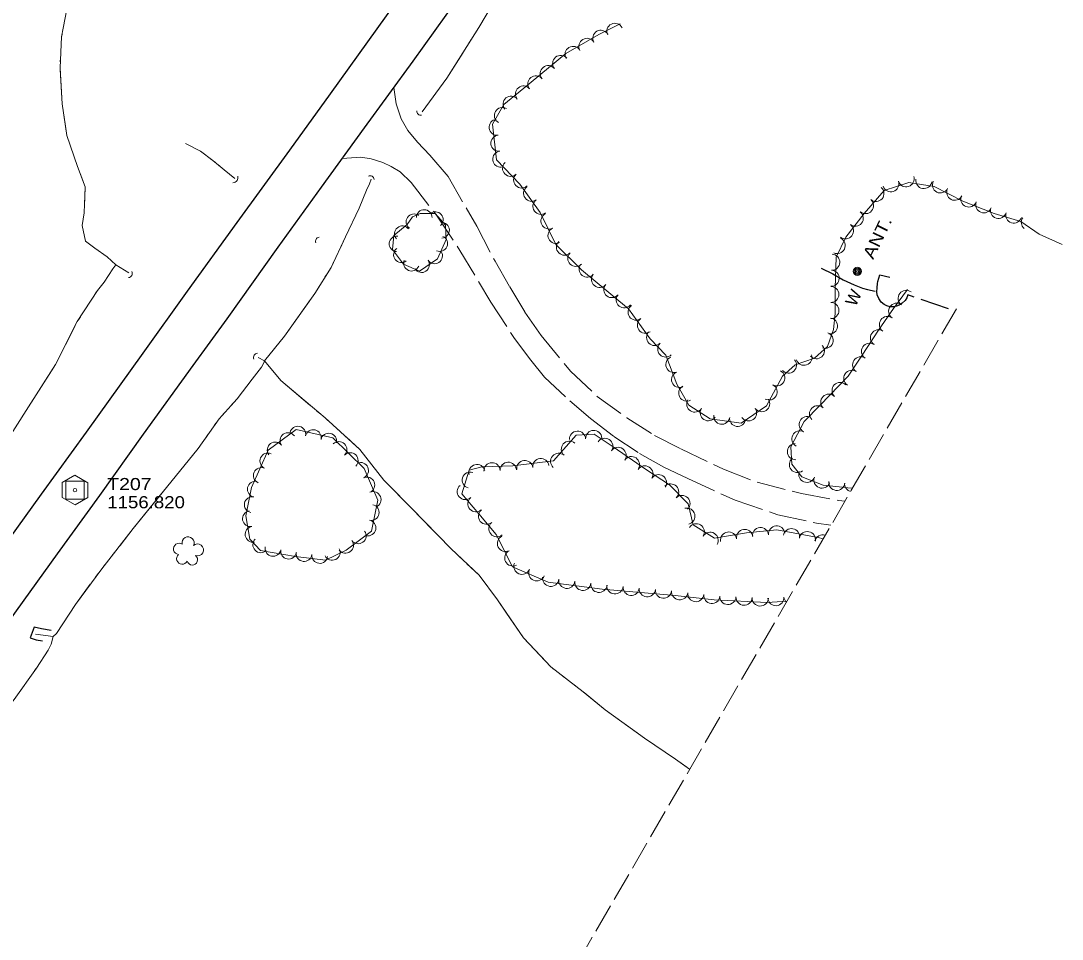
# Model space of a CAD drawing. Extents: x 300582 to 302999, y 51302 to 53600.
# Drawn here: x 301953 to 302469, y 52259 to 52714 of the extents above; entities that cross this region are included whole.
import ezdxf

# ---------------------------------------------------------------- set-up
doc = ezdxf.new("R2010")
doc.units = 0
doc.header["$LTSCALE"] = 2.4
doc.linetypes.add('LONG_DASHED', pattern=[7.5, 6, -1.5])
for name, color, linetype, lineweight in [('11', 7, 'Continuous', 25), ('12', 7, 'LONG_DASHED', 25), ('14', 7, 'Continuous', 13), ('15', 7, 'Continuous', 13), ('17', 7, 'LONG_DASHED', 13), ('18', 7, 'Continuous', 13), ('19', 7, 'Continuous', 13), ('4', 7, 'Continuous', 13), ('5', 7, 'Continuous', 13)]:
    doc.layers.add(name, color=color, linetype=linetype, lineweight=lineweight)

msp = doc.modelspace()

# ---------------------------------------------------------------- linework, layer by layer
at = {"layer": '11'}
for points in [[(301790.631, 52240.188), (301811.362, 52268.952), (301834.758, 52301.902), (301855.568, 52330.847), (301876.524, 52359.962), (301895.034, 52385.599), (301914.633, 52412.642), (301935.324, 52441.425), (301962.819, 52479.632), (301985.088, 52510.301), (302013.182, 52549.479), (302035.259, 52580.267), (302059.745, 52614.271), (302085.845, 52650.072), (302106.047, 52677.908), (302129.22, 52710.139), (302151.517, 52741.398), (302166.099, 52761.911), (302177.391, 52776.932)], [(301819.169, 52239.529), (301841.265, 52270.036), (301866.294, 52304.928), (301887.003, 52333.725), (301907.637, 52362.366), (301930.485, 52394.198), (301950.448, 52421.855), (301970.827, 52449.98), (301991.782, 52478.95), (302013.431, 52509.265), (302038.019, 52543.286), (302054.779, 52566.538), (302080.08, 52602.004), (302101.586, 52631.767), (302122.935, 52661.135), (302147.043, 52694.203), (302168.841, 52724.743), (302184.37, 52746.358), (302194.801, 52761.275)]]:
    msp.add_lwpolyline(points, dxfattribs=at)
at = {"layer": '12'}
msp.add_lwpolyline([(302412.324, 52571.355), (302392.142, 52578.364), (302391.592, 52576.882), (302390.82, 52575.633), (302389.309, 52574.188), (302387.835, 52573.282), (302386.511, 52572.674), (302385.176, 52572.419), (302383.431, 52572.401), (302381.791, 52572.936), (302380.474, 52573.541), (302378.989, 52574.814), (302377.734, 52576.481), (302377, 52578.314), (302376.818, 52579.921), (302376.887, 52581.821), (302377.109, 52583.93), (302377.344, 52585.019), (302378.297, 52588.252), (302383.199, 52587.174)], dxfattribs=at)
at = {"layer": '14'}
for centre, radius in [((302367.131, 52590.036), 2.018), ((302367.119, 52590.041), 1.518), ((302367.155, 52590.023), 1.008), ((302367.149, 52590.032), 0.502)]:
    msp.add_circle(centre, radius, dxfattribs=at)
at = {"layer": '15', "lineweight": 25}
for points in [[(302349.178, 52591.663), (302354.932, 52588.828), (302360.017, 52585.876), (302365.531, 52583.276), (302369.747, 52581.65), (302372.103, 52580.941), (302375.904, 52580.21)], [(301967.692, 52412.047), (301962.906, 52412.842), (301959.178, 52413.746), (301957.319, 52408.44), (301960.295, 52407.459), (301963.346, 52406.897)]]:
    msp.add_lwpolyline(points, dxfattribs=at)
at = {"layer": '15'}
for centre, radius, start, end in [((302150.768, 52669.29), 1.964, 175.22165, 281.46122), ((302057.698, 52636.468), 2.529, 270.89891, 17.13847), ((302125.64, 52635.321), 2.043, 6.63435, 112.87391), ((302100.624, 52604.928), 1.993, 96.56607, 202.80563), ((302005.683, 52589.08), 2.18, 277.01434, 23.25391), ((302070.086, 52547.318), 2.165, 94.45138, 200.69094)]:
    msp.add_arc(centre, radius, start, end, dxfattribs=at)
at = {"layer": '17'}
for points in [[(302137.507, 52681.123), (302138.673, 52672.939), (302141.046, 52665.53), (302144.429, 52659.784), (302149.198, 52653.947), (302155.256, 52647.592), (302164.29, 52637), (302178.497, 52612.321), (302187.622, 52595.048), (302194.853, 52582.339), (302202.405, 52569.785), (302210.437, 52558.284), (302225.023, 52540.531), (302238.225, 52528.068), (302252.906, 52517.475), (302266.565, 52508.757), (302279.686, 52502.085), (302300.759, 52491.925), (302317.47, 52485.522), (302339.406, 52479.863), (302357.802, 52476.441), (302361.026, 52476.221)], [(302111.903, 52645.959), (302121.155, 52646.61), (302126.158, 52645.743), (302131.979, 52643.853), (302136.164, 52642), (302140.654, 52639.315), (302146, 52633.97), (302158.84, 52617.405), (302170.188, 52600.391), (302185.544, 52574.768), (302197.193, 52556.794), (302205.28, 52546.034), (302212.064, 52537.611), (302224.644, 52525.831), (302234.848, 52517.023), (302246.446, 52508.186), (302259.104, 52499.789), (302271.315, 52493.01), (302283.18, 52487.312), (302306.521, 52476.667), (302327.66, 52469.374), (302346.864, 52465.211), (302354.049, 52464.179)]]:
    msp.add_lwpolyline(points, dxfattribs=at)
at = {"layer": '18'}
for points in [[(302249.628, 52712.569), (302238.953, 52707.292), (302222.714, 52697.865), (302205.556, 52683.77), (302191.988, 52672.657), (302186.375, 52662.958), (302188.337, 52645.265), (302199.911, 52633.177), (302209.887, 52619.215), (302217.684, 52603.332), (302230.387, 52590.71), (302253.707, 52571.451), (302264.408, 52556.546), (302272.204, 52548.49), (302277.647, 52534.184), (302283.552, 52523.63), (302294.168, 52516.886), (302309.541, 52514.798), (302322.05, 52523.456), (302330.068, 52538.117), (302336.272, 52543.702), (302345.958, 52547.034), (302352.309, 52552.847), (302355.269, 52561.217), (302356.12, 52569.16), (302356.053, 52581.657), (302356.65, 52597.022), (302361.478, 52607.004), (302370.544, 52618.585), (302380.398, 52630.129), (302392.614, 52634.076), (302405.19, 52632.076), (302419.383, 52624.752), (302434.98, 52618.675), (302448.151, 52614.661), (302457.265, 52608.373), (302468.617, 52603.279)], [(302392.05, 52581.082), (302384.967, 52571.586), (302377.562, 52560.885), (302369.438, 52548.508), (302362.6, 52538.089), (302348.629, 52523.702), (302340.733, 52515.668), (302334.219, 52502.986), (302334.651, 52494.407), (302339.646, 52488.162), (302350.191, 52484.105), (302361.258, 52482.918), (302362.367, 52482.776), (302364.752, 52482.654)], [(302350.187, 52457.513), (302347.789, 52458.215), (302327.162, 52462.01), (302312.228, 52460.438), (302296.382, 52457.867), (302285.831, 52464.342), (302283.282, 52474.851), (302274.015, 52484.283), (302262.632, 52491.644), (302246.197, 52503), (302236.784, 52509.315), (302227.795, 52508.899), (302216.623, 52496.201), (302196.347, 52493.628), (302181.116, 52493.111), (302174.693, 52491.524), (302171.116, 52479.77), (302179.643, 52469.913), (302188.121, 52459.703), (302196.293, 52443.57), (302213.917, 52435.96), (302240.753, 52432.623), (302276.882, 52429.399), (302296.164, 52427.182), (302322.431, 52425.924), (302332.313, 52426.66)]]:
    msp.add_lwpolyline(points, dxfattribs=at)
for points in [[(302137.384, 52607.695), (302136.765, 52600.748), (302142.252, 52593.56), (302150.106, 52590.163), (302159.052, 52596.14), (302163.322, 52605.744), (302163.02, 52612.922), (302158.003, 52618.655), (302150.472, 52618.726), (302146.639, 52616.946), (302144.021, 52613.189)], [(302088.796, 52448.664), (302103.507, 52446.837), (302113.786, 52451.921), (302126.385, 52461.324), (302129.565, 52476.575), (302122.812, 52492.257), (302107.261, 52507.518), (302088.998, 52511.634), (302075.19, 52501.484), (302066.937, 52482.97), (302064.084, 52468.804), (302066.038, 52457.317), (302071.32, 52451.775)]]:
    msp.add_lwpolyline(points, close=True, dxfattribs=at)
for centre, radius, start, end in [((302246.987, 52708.943), 3.975, 26.31235, 206.29703), ((302233.109, 52701.494), 3.975, 30.14351, 210.12819), ((302239.984, 52705.485), 3.975, 30.14351, 210.12819), ((302226.235, 52697.503), 3.975, 30.14351, 210.12819), ((302220.105, 52693.029), 3.975, 39.41018, 219.39485), ((302213.963, 52687.983), 3.975, 39.41018, 219.39485), ((302207.82, 52682.938), 3.975, 39.41018, 219.39485), ((302201.67, 52677.898), 3.975, 39.32718, 219.31186), ((302195.52, 52672.861), 3.975, 39.32718, 219.31186), ((302191.24, 52667.212), 3.975, 59.94886, 239.93354), ((302188.644, 52661.368), 3.975, 96.33541, 276.32009), ((302189.521, 52653.468), 3.975, 96.33541, 276.32009), ((302190.397, 52645.567), 3.975, 96.33541, 276.32009), ((302195.286, 52641.015), 3.975, 133.76324, 313.74792), ((302200.784, 52635.274), 3.975, 133.76324, 313.74792), ((302383.711, 52633.386), 3.975, 197.91335, 17.89803), ((302391.275, 52635.83), 3.975, 197.91335, 17.89803), ((302400.065, 52634.998), 3.975, 170.97141, 350.95609), ((302408.303, 52632.811), 3.975, 152.71261, 332.69729), ((302205.695, 52628.66), 3.975, 125.55388, 305.53856), ((302376.352, 52628.593), 3.975, 229.52347, 49.50815), ((302415.366, 52629.166), 3.975, 152.71261, 332.69729), ((302210.317, 52622.192), 3.975, 125.55388, 305.53856), ((302371.191, 52622.547), 3.975, 229.52347, 49.50815), ((302422.333, 52625.835), 3.975, 158.72047, 338.70515), ((302429.74, 52622.949), 3.975, 158.72047, 338.70515), ((302147.439, 52614.532), 3.891, 55.13762, 235.1223), ((302152.485, 52616.67), 3.891, 359.46751, 179.45219), ((302157.974, 52615.596), 3.891, 311.19713, 131.1818), ((302214.3, 52614.947), 3.975, 116.15419, 296.13886), ((302366.123, 52616.312), 3.975, 231.95262, 51.93729), ((302437.035, 52620.224), 3.975, 163.05851, 343.04319), ((302444.639, 52617.906), 3.975, 163.05851, 343.04319), ((302141.68, 52608.607), 3.891, 39.62506, 219.60974), ((302161.088, 52610.392), 3.891, 272.41685, 92.40152), ((302361.223, 52610.053), 3.975, 231.95262, 51.93729), ((302452.331, 52614.304), 3.975, 145.4048, 231.37281), ((302139.067, 52603.638), 3.891, 84.91587, 264.90055), ((302160.224, 52603.79), 3.891, 246.03743, 66.0221), ((302217.803, 52607.811), 3.975, 116.15419, 296.13886), ((302221.974, 52602.002), 3.975, 135.19092, 315.17559), ((302357.121, 52602.774), 3.975, 244.19597, 64.18065), ((302141.235, 52598.249), 3.891, 127.36417, 307.34885), ((302157.658, 52597.658), 3.891, 213.75533, 33.74001), ((302227.613, 52596.399), 3.975, 135.19092, 315.17559), ((302354.472, 52594.539), 3.975, 267.78258, 87.76726), ((302146.215, 52594.065), 3.891, 156.61829, 336.60297), ((302151.188, 52593.335), 3.891, 213.75533, 33.74001), ((302233.231, 52591.059), 3.975, 140.45581, 320.44048), ((302239.36, 52585.997), 3.975, 140.45581, 320.44048), ((302354.163, 52586.596), 3.975, 267.78258, 87.76726), ((302245.489, 52580.936), 3.975, 140.45581, 320.44048), ((302353.989, 52578.558), 3.975, 270.31484, 90.29952), ((302251.618, 52575.874), 3.975, 140.45581, 320.44048), ((302391.336, 52576.619), 4.005, 53.28866, 233.27334), ((302257.451, 52569.803), 3.975, 125.68401, 305.66868), ((302354.032, 52570.61), 3.975, 270.31484, 90.29952), ((302386.596, 52570.256), 4.005, 55.32476, 235.30944), ((302262.087, 52563.346), 3.975, 125.68401, 305.66868), ((302353.36, 52562.93), 3.975, 263.89241, 83.87709), ((302382.038, 52563.67), 4.005, 55.32476, 235.30944), ((302377.574, 52557.084), 4.005, 56.72762, 236.71229), ((302266.648, 52557.223), 3.975, 134.068, 314.05268), ((302351.158, 52555.831), 3.975, 250.53183, 70.51651), ((302272.176, 52551.511), 3.975, 134.068, 314.05268), ((302346.833, 52550.655), 3.975, 222.47518, 42.45986), ((302373.18, 52550.388), 4.005, 56.72762, 236.71229), ((302276.196, 52543.847), 3.975, 110.83797, 290.82264), ((302332.974, 52543.532), 3.975, 222.00202, 41.98669), ((302340.687, 52547.421), 3.975, 198.99096, 18.97564), ((302368.785, 52543.693), 4.005, 56.73073, 236.71541), ((302279.023, 52536.418), 3.975, 110.83797, 290.82264), ((302327.203, 52537.215), 3.975, 241.33372, 61.31839), ((302364.391, 52536.998), 4.005, 56.73073, 236.71541), ((302358.573, 52530.934), 4.005, 45.84811, 225.83278), ((302282.563, 52529.658), 3.975, 119.23483, 299.21951), ((302323.389, 52530.241), 3.975, 241.33372, 61.31839), ((302286.529, 52524.203), 3.975, 147.58119, 327.56587), ((302319.753, 52524.396), 3.975, 214.69638, 34.68106), ((302352.994, 52525.188), 4.005, 45.84811, 225.83278), ((302293.239, 52519.941), 3.975, 147.58119, 327.56587), ((302313.217, 52519.872), 3.975, 214.69638, 34.68106), ((302347.389, 52519.45), 4.005, 45.504, 225.48868), ((302299.924, 52518.204), 3.975, 172.27293, 352.25761), ((302307.801, 52517.134), 3.975, 172.27293, 352.25761), ((302342.302, 52514.136), 4.005, 62.82075, 242.80543), ((302084.981, 52506.132), 3.925, 36.32657, 216.31124), ((302089.868, 52509.332), 3.925, 347.3069, 167.29158), ((302097.525, 52507.606), 3.925, 347.3069, 167.29158), ((302105.183, 52505.88), 3.925, 347.3069, 167.29158), ((302228.446, 52506.823), 4.019, 2.65735, 182.64203), ((302236.475, 52507.195), 4.019, 2.65735, 182.64203), ((302338.643, 52507.012), 4.005, 62.82075, 242.80543), ((302078.657, 52501.482), 3.925, 36.32657, 216.31124), ((302110.235, 52501.721), 3.925, 315.54691, 135.53159), ((302224.432, 52501.891), 4.019, 48.66558, 228.65026), ((302241.949, 52503.317), 4.019, 326.15076, 146.13544), ((302336.433, 52500.688), 4.005, 92.89039, 272.87506), ((302075.007, 52496.028), 3.925, 65.98175, 245.96643), ((302115.837, 52496.223), 3.925, 315.54691, 135.53159), ((302219.122, 52495.857), 4.019, 48.66558, 228.65026), ((302248.566, 52498.806), 4.019, 325.36457, 145.34925), ((302120.962, 52491.359), 3.925, 293.30539, 113.29007), ((302178.595, 52490.321), 4.019, 13.88638, 193.87106), ((302186.106, 52491.176), 4.019, 1.95176, 181.93644), ((302194.139, 52491.448), 4.019, 1.95176, 181.93644), ((302202.322, 52492.266), 4.019, 7.23977, 187.22445), ((302210.296, 52493.278), 4.019, 7.23977, 187.22445), ((302255.179, 52494.237), 4.019, 325.36457, 145.34925), ((302261.852, 52489.643), 4.019, 327.11828, 147.10296), ((302337.428, 52494.291), 4.005, 128.66188, 308.64655), ((302071.811, 52488.859), 3.925, 65.98175, 245.96643), ((302124.067, 52484.149), 3.925, 293.30539, 113.29007), ((302175.384, 52486.571), 4.019, 73.08151, 253.06618), ((302268.601, 52485.279), 4.019, 327.11828, 147.10296), ((302342.113, 52489.459), 4.005, 158.96433, 338.949), ((302068.855, 52482.087), 3.925, 78.62075, 258.60543), ((302172.896, 52480.928), 4.019, 130.86978, 310.85446), ((302274.583, 52480.704), 4.019, 314.5021, 134.48678), ((302349.588, 52486.583), 4.005, 158.96433, 338.949), ((302356.933, 52485.49), 4.005, 173.88576, 353.87044), ((302364.788, 52484.751), 4.005, 177.07257, 254.67673), ((302067.305, 52474.392), 3.925, 78.62075, 258.60543), ((302127.171, 52476.939), 3.925, 293.30539, 113.29007), ((302178.154, 52474.849), 4.019, 130.86978, 310.85446), ((302280.215, 52474.971), 4.019, 314.5021, 134.48678), ((302126.213, 52470.564), 3.925, 258.22962, 78.2143), ((302282.606, 52468.716), 4.019, 283.64168, 103.62636), ((302066.4, 52467.437), 3.925, 99.66157, 279.64625), ((302183.389, 52468.695), 4.019, 129.71263, 309.69731), ((302067.717, 52459.699), 3.925, 99.66157, 279.64625), ((302124.611, 52462.88), 3.925, 258.22962, 78.2143), ((302188.523, 52462.511), 4.019, 129.71263, 309.69731), ((302287.31, 52460.966), 4.019, 328.47081, 148.45549), ((302319.155, 52459.052), 4.019, 6.01667, 186.00134), ((302327.149, 52459.893), 4.019, 6.01667, 186.00134), ((302334.455, 52458.529), 4.019, 349.58284, 169.56752), ((302035.504, 52455.506), 2.974, 332.49313, 193.72701), ((302071.515, 52454.548), 3.925, 133.63164, 313.61632), ((302119.796, 52458.97), 3.925, 216.74271, 36.72739), ((302192.769, 52455.181), 4.019, 116.87167, 296.85635), ((302294.161, 52456.762), 4.019, 328.47081, 148.45549), ((302303.354, 52456.867), 4.019, 9.22354, 189.20822), ((302311.288, 52458.154), 4.019, 9.22354, 189.20822), ((302342.36, 52457.075), 4.019, 349.58284, 169.56752), ((302349.986, 52455.381), 4.019, 72.77434, 163.68449), ((302031.041, 52452.513), 2.777, 55.46402, 263.23701), ((302040.178, 52451.981), 2.975, 250.14395, 133.11722), ((302077.564, 52452.75), 3.925, 169.91386, 349.89854), ((302085.292, 52451.374), 3.925, 169.91386, 349.89854), ((302106.899, 52450.807), 3.925, 206.32469, 26.30937), ((302113.505, 52454.275), 3.925, 216.74271, 36.72739), ((302032.581, 52447.691), 2.783, 132.14104, 333.15208), ((302037.589, 52447.104), 2.611, 194.84918, 52.78179), ((302092.945, 52450.219), 3.925, 172.92819, 352.91287), ((302100.734, 52449.252), 3.925, 172.92819, 352.91287), ((302196.401, 52448.011), 4.019, 116.87167, 296.85635), ((302200.913, 52443.866), 4.019, 156.65309, 336.63777), ((302208.292, 52440.68), 4.019, 156.65309, 336.63777), ((302215.171, 52437.924), 4.019, 172.91944, 352.90411), ((302223.148, 52436.932), 4.019, 172.91944, 352.90411), ((302231.124, 52435.94), 4.019, 172.91944, 352.90411), ((302239.1, 52434.948), 4.019, 172.91944, 352.90411), ((302247.026, 52434.175), 4.019, 174.90833, 354.89301), ((302255.031, 52433.461), 4.019, 174.90833, 354.89301), ((302263.037, 52432.746), 4.019, 174.90833, 354.89301), ((302271.043, 52432.032), 4.019, 174.90833, 354.89301), ((302279.096, 52431.262), 4.019, 173.44872, 353.4334), ((302287.081, 52430.344), 4.019, 173.44872, 353.4334), ((302295.066, 52429.426), 4.019, 173.44872, 353.4334), ((302302.947, 52428.963), 4.019, 177.2657, 357.25038), ((302310.976, 52428.579), 4.019, 177.2657, 357.25038), ((302319.004, 52428.194), 4.019, 177.2657, 357.25038), ((302326.768, 52428.356), 4.019, 184.26449, 4.24917), ((302334.783, 52428.953), 4.019, 184.26449, 225.68569)]:
    msp.add_arc(centre, radius, start, end, dxfattribs=at)
at = {"layer": '19'}
for p, q in [((302174.406, 52702.702), (302175.723, 52704.795)), ((301972.476, 52699.666), (301972.573, 52701.61)), ((301972.186, 52693.833), (301972.283, 52695.777)), ((302045.458, 52646.66), (302044.851, 52647.106)), ((302047.28, 52645.323), (302046.672, 52645.769)), ((302049.044, 52643.912), (302048.464, 52644.393)), ((301984.415, 52629.459), (301984.492, 52631.404)), ((301984.182, 52623.625), (301984.26, 52625.57)), ((302107.277, 52593.863), (302108.388, 52596.24)), ((302103.311, 52587.078), (302104.714, 52589.296)), ((302099.105, 52580.426), (302100.507, 52582.644)), ((301986.797, 52574.771), (301987.735, 52576.225)), ((301983.981, 52570.409), (301984.92, 52571.863)), ((301981.166, 52566.047), (301982.104, 52567.501)), ((302052, 52518.195), (302053.474, 52519.828)), ((302099.172, 52520.973), (302100.833, 52519.57)), ((302048.034, 52512.932), (302049.305, 52514.727)), ((302104.132, 52516.74), (302105.743, 52515.282)), ((302044.223, 52507.545), (302045.494, 52509.341)), ((302108.967, 52512.366), (302110.578, 52510.908)), ((302159.701, 52458.852), (302161.215, 52457.292)), ((302164.242, 52454.173), (302165.756, 52452.614)), ((301997.711, 52449.01), (301999.069, 52450.74)), ((302168.915, 52449.629), (302170.497, 52448.14)), ((301993.637, 52443.82), (301994.995, 52445.55)), ((301989.671, 52438.547), (301990.983, 52440.312)), ((302216.267, 52393.312), (302217.988, 52391.984)), ((301956.07, 52387.387), (301957.188, 52388.98)), ((302221.43, 52389.33), (302223.152, 52388.002)), ((302226.594, 52385.348), (302228.315, 52384.02)), ((301952.715, 52382.609), (301953.833, 52384.202))]:
    msp.add_line(p, q, dxfattribs=at)
for points in [[(302151.425, 52669.01), (302163.696, 52685.682), (302179.523, 52710.833), (302189.505, 52727.654), (302199.512, 52740.166), (302203.84, 52747.555), (302206.342, 52751.117)], [(301999.656, 52593.244), (301995.346, 52597.263), (301989.334, 52601.421), (301984.741, 52604.903), (301983.048, 52612.702), (301983.997, 52618.982), (301984.514, 52631.952), (301980.664, 52641.995), (301975.4, 52657.327), (301973.027, 52672.97), (301972.04, 52690.883), (301972.8, 52706.187), (301976.095, 52723.389), (301977.086, 52739.224)], [(301973.769, 52711.246), (301976.095, 52723.389), (301977.086, 52739.224)], [(302178.358, 52708.982), (302179.523, 52710.833), (302179.669, 52711.079)], [(301972.766, 52705.498), (301972.8, 52706.187), (301973.037, 52707.422)], [(302151.425, 52669.01), (302163.696, 52685.682), (302171.771, 52698.515)], [(301974.71, 52661.875), (301973.027, 52672.97), (301972.092, 52689.944)], [(301983.317, 52635.074), (301980.664, 52641.995), (301975.4, 52657.327), (301974.71, 52661.875)], [(302058.643, 52636.015), (302053.339, 52640.353), (302047.814, 52644.931), (302041.61, 52649.485), (302034.143, 52653.359)], [(302043.636, 52647.998), (302041.61, 52649.485), (302034.143, 52653.359)], [(302058.643, 52636.015), (302053.339, 52640.353), (302050.204, 52642.951)], [(302073.341, 52545.669), (302083.214, 52557.87), (302098.259, 52579.089), (302106.358, 52591.896), (302113.441, 52607.054), (302120.242, 52621.265), (302123.93, 52630.219), (302125.349, 52633.395), (302126.192, 52635.653)], [(302110.609, 52600.994), (302113.441, 52607.054), (302120.242, 52621.265), (302123.93, 52630.219), (302125.349, 52633.395), (302126.192, 52635.653)], [(301983.819, 52617.805), (301983.997, 52618.982), (301984.027, 52619.736)], [(301999.656, 52593.244), (301995.346, 52597.263), (301989.334, 52601.421), (301984.741, 52604.903), (301983.048, 52612.702), (301983.238, 52613.959)], [(301893.643, 52423.917), (301898.802, 52432.342), (301910.08, 52449.662), (301927.094, 52475.816), (301939.111, 52495.715), (301955.302, 52521.101), (301969.796, 52543.795), (301980.589, 52565.153), (301990.538, 52580.567), (301993.861, 52584.665), (301998.139, 52591.278), (301999.656, 52593.244), (302006.211, 52589.33)], [(301989.612, 52579.132), (301990.538, 52580.567), (301993.861, 52584.665), (301998.139, 52591.278), (301999.656, 52593.244), (302006.211, 52589.33)], [(302073.341, 52545.669), (302083.214, 52557.87), (302096.138, 52576.098)], [(301967.877, 52540.791), (301969.796, 52543.795), (301979.508, 52563.013)], [(301968.679, 52409.012), (301970.254, 52410.543), (301979.626, 52425.026), (301992.742, 52442.68), (302008.321, 52462.526), (302022.589, 52480.246), (302040.426, 52502.179), (302050.884, 52516.959), (302059.861, 52526.903), (302067.249, 52536.551), (302071.905, 52542.508), (302073.076, 52544.752), (302073.341, 52545.669), (302070.155, 52547.25)], [(302056.421, 52523.093), (302059.861, 52526.903), (302067.249, 52536.551), (302071.905, 52542.508), (302073.076, 52544.752), (302073.341, 52545.669), (302070.155, 52547.25)], [(302073.341, 52545.669), (302081.423, 52535.959), (302095.851, 52523.777)], [(302073.341, 52545.669), (302081.423, 52535.959), (302103.387, 52517.414), (302120.653, 52501.794), (302132.476, 52486.623), (302146.267, 52472.692), (302165.878, 52452.488), (302179.757, 52439.422), (302188.819, 52427.184), (302201.626, 52408.381), (302215.241, 52394.103), (302231.329, 52381.696), (302242.203, 52372.831), (302261.664, 52358.702), (302277, 52348.297), (302284.031, 52343.319)], [(301954.37, 52519.64), (301955.302, 52521.101), (301967.877, 52540.791)], [(302021.681, 52479.119), (302022.589, 52480.246), (302040.426, 52502.179), (302041.682, 52503.954)], [(302113.802, 52507.992), (302120.653, 52501.794), (302132.476, 52486.623), (302134.611, 52484.466)], [(302134.611, 52484.466), (302146.267, 52472.692), (302156.674, 52461.971)], [(302001.785, 52454.2), (302008.321, 52462.526), (302021.681, 52479.119)], [(302173.661, 52445.161), (302179.757, 52439.422), (302188.819, 52427.184), (302193.272, 52420.646)], [(301968.679, 52409.012), (301970.254, 52410.543), (301979.626, 52425.026), (301987.048, 52435.015)], [(302193.272, 52420.646), (302201.626, 52408.381), (302213.135, 52396.311)], [(301791.906, 52163.721), (301809.482, 52187.79), (301830.94, 52216.555), (301851.723, 52245.836), (301871.798, 52273.721), (301892.388, 52301.74), (301912.128, 52328.766), (301929.268, 52352.195), (301949.377, 52377.856), (301960.301, 52393.412), (301966.147, 52402.343), (301967.688, 52405.372), (301968.679, 52409.012), (301959.948, 52410.257)], [(301959.425, 52392.165), (301960.301, 52393.412), (301966.147, 52402.343), (301967.688, 52405.372), (301968.679, 52409.012), (301959.948, 52410.257)], [(302231.748, 52381.354), (302242.203, 52372.831), (302256.79, 52362.24)], [(302256.79, 52362.24), (302261.664, 52358.702), (302277, 52348.297), (302282.671, 52344.282)]]:
    msp.add_lwpolyline(points, dxfattribs=at)
at = {"layer": '4', "linetype": 'LONG_DASHED'}
msp.add_line((301858.628, 51609.011), (302416.216, 52571.488), dxfattribs=at)
at = {"layer": '5'}
for points in [[(301973.026, 52485.383), (301973.026, 52477.992), (301979.486, 52474.265), (301985.883, 52477.93), (301985.883, 52485.259), (301979.361, 52488.985)], [(301974.94, 52477.12), (301974.94, 52486.12), (301983.94, 52486.12), (301983.94, 52477.12)]]:
    msp.add_lwpolyline(points, close=True, dxfattribs=at)
msp.add_circle((301979.44, 52481.62), 0.871, dxfattribs=at)

# ---------------------------------------------------------------- texts
at = {"layer": '14', "width": 1.2}
msp.add_text('ANT.', height=6, rotation=64.069, dxfattribs=at).set_placement((302374.945, 52595.553))
at = {"layer": '15'}
msp.add_text('W', height=6, rotation=64.069, dxfattribs=at).set_placement((302366.243, 52572.193))
at = {"layer": '5'}
for s, width, p in [('T207', 1.2, (301995.44, 52481.62)), ('1156.820', 1.15, (301995.44, 52472.62))]:
    msp.add_text(s, height=6, dxfattribs=dict(at, width=width)).set_placement(p)

doc.saveas('drawing.dxf')
